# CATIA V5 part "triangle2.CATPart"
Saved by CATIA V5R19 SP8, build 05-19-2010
Part number: triangle2
Publications: "Droite.1", "Droite.2", "Droite.3", "axepivotri/bati", "axepivotri/tige", "axepivotri/bras", "axeglissieretri"
Bounding box of the stored display mesh (mm): x -20 to 20, y -80 to 150, z -50 to 50
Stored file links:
  C:\Users\rcousturie\Desktop\EU_thinkMotion\iao\IAO_MMS_Groupe1\flamrini\Lamrini_projet_IAO2011\Lamrini_projet_IAO2011\projet_iao_traindatterrissage\projet_iao_traindatterrissage\triangle2.CATPart
  C:\Users\rcousturie\Desktop\EU_thinkMotion\iao\IAO_MMS_Groupe1\flamrini\Lamrini_projet_IAO2011\Lamrini_projet_IAO2011\projet_iao_traindatterrissage\projet_iao_traindatterrissage\squelettetrain.CATProduct
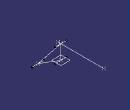
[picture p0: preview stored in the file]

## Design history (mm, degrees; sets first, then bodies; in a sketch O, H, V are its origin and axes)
Set1
  Line1: type PtPt, FirstPoint Point1, SecondPoint Point2
  Line2: type PtPt, FirstPoint Point2, SecondPoint Point3
  Line3: type PtPt, FirstPoint Point3, SecondPoint Point1
  Line4 "axepivotri/bati": type PtDir, RefPoint Point1, Direction yz-plane, Start -20, End 20
  Line5 "axepivotri/tige": type PtDir, RefPoint Point3, Direction Line4, Start -20, End 20
  Line6 "axepivotri/bras": type PtDir, RefPoint Point2, Direction yz-plane, Start -20, End 20
  Line7 "axeglissieretri": type PtPt, FirstPoint Point4, SecondPoint Point5
Set2
  Point1 "Pointb": linked copy from another document
  Point2 "PointB": linked copy from another document
  Point3 "PointE": linked copy from another document
  Point4: linked copy from another document
  Point5: linked copy from another document
Body1 (main body)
